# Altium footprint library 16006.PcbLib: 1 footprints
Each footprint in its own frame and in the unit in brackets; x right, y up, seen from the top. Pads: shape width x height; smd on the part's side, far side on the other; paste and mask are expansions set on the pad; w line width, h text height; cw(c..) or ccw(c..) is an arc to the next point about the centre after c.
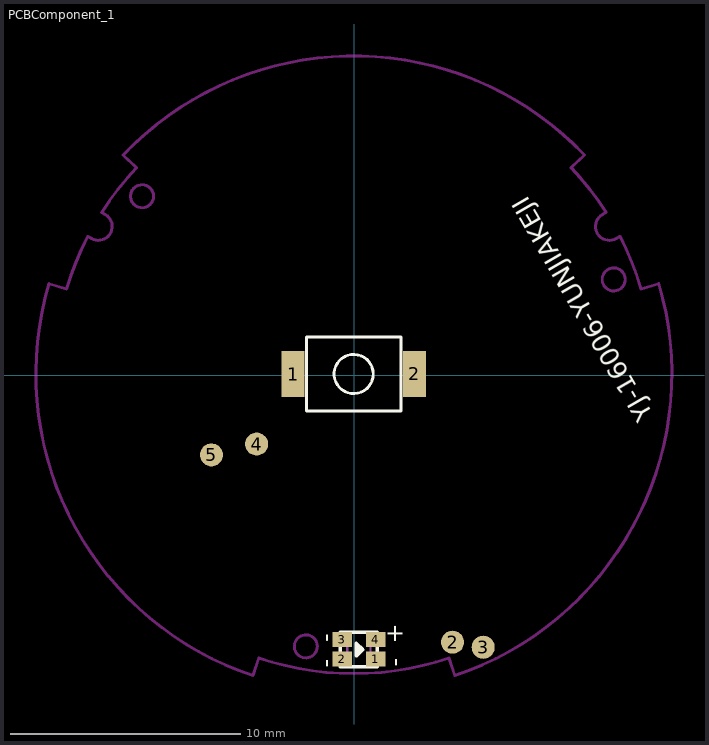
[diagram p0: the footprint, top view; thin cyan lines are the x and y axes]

## PCBComponent_1 [mm]
pads (10):
  rect 1x2 smd: 1(-2.647,0.058) 2(2.613,0.068)
  rect 0.85x0.65 smd paste+0: 1(0.935,-12.312) 2(-0.515,-12.312) 3(-0.515,-11.462) 4(0.935,-11.462)
  round 1 smd: 2(4.274,-11.574) 3(5.604,-11.794) 4(-4.228,-2.977) 5(-6.188,-3.447)
Top Overlay:
  circle w0.127: c-0.016,0.063 r0.85
  region: 0.09,-12.172 0.37,-11.892 0.09,-11.612
  lines w0.127: -2.066,-1.537 -2.066,1.663 2.034,1.663 2.034,-1.537 -2.066,-1.537
  lines w0.15: -0.59,-12.637 -0.59,-11.137 ; 1.01,-12.637 1.01,-11.137
  lines w0.152: -0.59,-12.637 1.01,-12.637 ; -0.59,-11.137 1.01,-11.137 ; 0.09,-12.172 0.37,-11.892 0.09,-11.612 0.09,-12.172
  text "-" at 2.115,-12.649 h0.76
  text "+" at 2.115,-11.633 h0.76
  text "-" at -0.89,-12.687 h0.76
  text "-" at -0.89,-11.587 h0.76
  text "YJ-16006-YUNJIAKEJI" at 13.004,-1.704 h0.8
Keep-Out Layer:
  circle w0.127: c-2.092,-11.754 r0.5
  circle w0.127: c11.268,4.168 r0.5
  circle w0.127: c-9.201,7.777 r0.5
  lines w0.127: -9.935,9.65 cw(c-0.008,0.063) 9.919,9.65 ; -13.241,3.983 ccw(c-0.009,0.064) -4.388,-13.023 -4.134,-12.264 ccw(c-0.009,0.064) 4.116,-12.264 4.369,-13.023 ccw(c-0.009,0.064) 13.222,3.983 12.455,3.756 ccw(c-0.009,0.064) 11.537,6.037 11.376,5.944 cw(c11.076,6.464) 10.776,6.984 10.937,7.077 ccw(c-0.009,0.064) 9.42,9.013 10.001,9.563 ccw(c-0.009,0.064) -10.02,9.563 -9.439,9.013 ccw(c-0.009,0.064) -10.956,7.077 -10.794,6.984 cw(c-11.095,6.464) -11.395,5.944 -11.556,6.037 ccw(c-0.009,0.064) -12.474,3.756 -13.241,3.983
Mechanical 7:
  lines w0.1: -0.29,-12.637 -0.29,-11.137 ; 0.71,-12.637 0.71,-11.137 ; -0.59,-12.637 -0.59,-11.137 1.01,-11.137 1.01,-12.637 -0.59,-12.637
3D body: height 0.36, standoff 0.18, extent -0.194,-11.656 0.106,-11.356
3D body: height 0.18, standoff 0, extent -0.59,-12.637 1.01,-11.137
3D body: height 0.55, standoff 0.18, extent -0.34,-12.637 0.76,-11.137
3D body: height 0.36, standoff 0.18, extent 0.314,-12.418 0.614,-12.118
3D body: height 0.36, standoff 0.18, extent -0.194,-12.418 0.106,-12.118
3D body: height 1.8, standoff 0, extent -2.072,-1.537 2.043,1.663
3D body: height 0.1, standoff 0, extent 2.017,-0.775 2.957,0.901
3D body: height 0.1, standoff 0, extent -3.024,-0.775 -2.085,0.901
3D body: height 2.3, standoff 1.8, extent -1.007,-0.935 0.985,1.061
